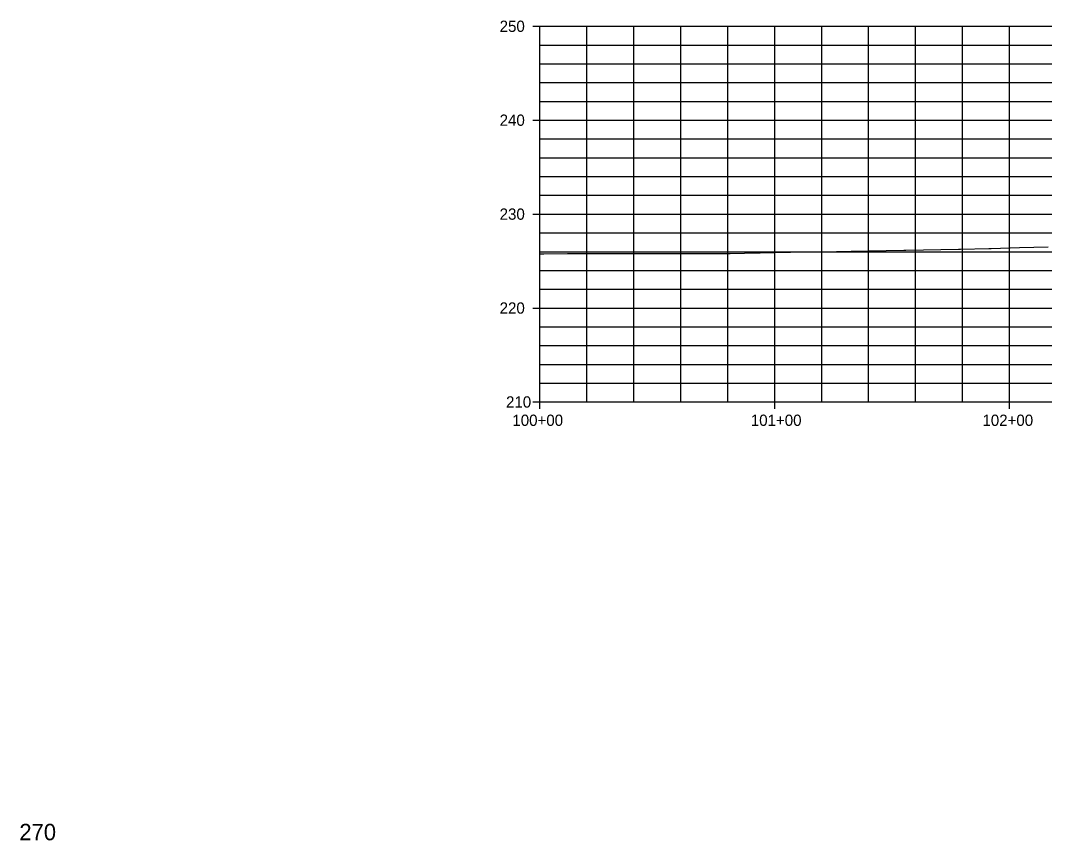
# Model space of a CAD drawing. Extents: x 1805251 to 1808760, y 516965 to 518393.
# Drawn here: x 1805251 to 1805687.1, y 518043.6 to 518392.9 of the extents above; entities that cross this region are included whole.
import ezdxf

# ---------------------------------------------------------------- set-up
doc = ezdxf.new("R2010")
doc.units = 0
for name, color, linetype in [('R_Axis', 7, 'Continuous'), ('R_Axis Annot', 7, 'Continuous'), ('R_Exist Surface', 7, 'Continuous'), ('R_Grid', 7, 'Continuous')]:
    doc.layers.add(name, color=color, linetype=linetype)

msp = doc.modelspace()

# ---------------------------------------------------------------- linework, layer by layer
at = {"layer": 'R_Axis'}
for q in [(1805472.2, 518390.42), (1806472.2, 518230.42)]:
    msp.add_line((1805472.2, 518230.42), q, dxfattribs=at)
at = {"layer": 'R_Exist Surface'}
msp.add_lwpolyline([(1805472.2, 518293.56), (1805473.66, 518293.55), (1805473.75, 518293.55), (1805473.84, 518293.55), (1805483.93, 518293.58), (1805493.56, 518293.59), (1805493.66, 518293.59), (1805513.21, 518293.6), (1805513.49, 518293.61), (1805513.76, 518293.61), (1805533.11, 518293.63), (1805533.57, 518293.64), (1805552.54, 518293.66), (1805553.18, 518293.67), (1805565.47, 518293.9), (1805566.06, 518293.91), (1805578.4, 518294.15), (1805578.94, 518294.16), (1805591.32, 518294.39), (1805591.82, 518294.4), (1805592.32, 518294.41), (1805604.7, 518294.65), (1805627.18, 518295.06), (1805628, 518295.07), (1805650.5, 518295.48), (1805651.29, 518295.5), (1805663.45, 518295.82), (1805664.33, 518295.84), (1805676.49, 518296.16), (1805688.59, 518296.47)], dxfattribs=at)
at = {"layer": 'R_Grid'}
for p, q in [((1805469.2, 518390.42), (1805472.2, 518390.42)), ((1805469.2, 518390.42), (1805472.2, 518390.42)), ((1805472.2, 518390.42), (1806472.2, 518390.42)), ((1805472.2, 518390.42), (1806472.2, 518390.42)), ((1805492.2, 518230.42), (1805492.2, 518390.42)), ((1805512.2, 518230.42), (1805512.2, 518390.42)), ((1805532.2, 518230.42), (1805532.2, 518390.42)), ((1805552.2, 518230.42), (1805552.2, 518390.42)), ((1805572.2, 518230.42), (1805572.2, 518390.42)), ((1805592.2, 518230.42), (1805592.2, 518390.42)), ((1805612.2, 518230.42), (1805612.2, 518390.42)), ((1805632.2, 518230.42), (1805632.2, 518390.42)), ((1805652.2, 518230.42), (1805652.2, 518390.42)), ((1805672.2, 518230.42), (1805672.2, 518390.42)), ((1805472.2, 518382.42), (1805473.7, 518382.42)), ((1805472.2, 518382.42), (1806472.2, 518382.42)), ((1805472.2, 518374.42), (1805473.7, 518374.42)), ((1805472.2, 518374.42), (1806472.2, 518374.42)), ((1805472.2, 518366.42), (1805473.7, 518366.42)), ((1805472.2, 518366.42), (1806472.2, 518366.42)), ((1805472.2, 518358.42), (1805473.7, 518358.42)), ((1805472.2, 518358.42), (1806472.2, 518358.42)), ((1805469.2, 518350.42), (1805472.2, 518350.42)), ((1805472.2, 518350.42), (1806472.2, 518350.42)), ((1805472.2, 518342.42), (1805473.7, 518342.42)), ((1805472.2, 518342.42), (1806472.2, 518342.42)), ((1805472.2, 518334.42), (1805473.7, 518334.42)), ((1805472.2, 518334.42), (1806472.2, 518334.42)), ((1805472.2, 518326.42), (1805473.7, 518326.42)), ((1805472.2, 518326.42), (1806472.2, 518326.42)), ((1805472.2, 518318.42), (1805473.7, 518318.42)), ((1805472.2, 518318.42), (1806472.2, 518318.42)), ((1805469.2, 518310.42), (1805472.2, 518310.42)), ((1805472.2, 518310.42), (1806472.2, 518310.42)), ((1805472.2, 518302.42), (1805473.7, 518302.42)), ((1805472.2, 518302.42), (1806472.2, 518302.42)), ((1805472.2, 518294.42), (1805473.7, 518294.42)), ((1805472.2, 518294.42), (1806472.2, 518294.42)), ((1805472.2, 518286.42), (1805473.7, 518286.42)), ((1805472.2, 518286.42), (1806472.2, 518286.42)), ((1805472.2, 518278.42), (1805473.7, 518278.42)), ((1805472.2, 518278.42), (1806472.2, 518278.42)), ((1805469.2, 518270.42), (1805472.2, 518270.42)), ((1805472.2, 518270.42), (1806472.2, 518270.42)), ((1805472.2, 518262.42), (1805473.7, 518262.42)), ((1805472.2, 518262.42), (1806472.2, 518262.42)), ((1805472.2, 518254.42), (1805473.7, 518254.42)), ((1805472.2, 518254.42), (1806472.2, 518254.42)), ((1805472.2, 518246.42), (1805473.7, 518246.42)), ((1805472.2, 518246.42), (1806472.2, 518246.42)), ((1805472.2, 518238.42), (1805473.7, 518238.42)), ((1805472.2, 518238.42), (1806472.2, 518238.42)), ((1805469.2, 518230.42), (1805472.2, 518230.42)), ((1805472.2, 518227.42), (1805472.2, 518230.42)), ((1805572.2, 518227.42), (1805572.2, 518230.42)), ((1805672.2, 518227.42), (1805672.2, 518230.42))]:
    msp.add_line(p, q, dxfattribs=at)

# ---------------------------------------------------------------- texts
at = {"layer": 'R_Axis Annot'}
for s, height, p in [('250', 4.8, (1805455.05, 518388.02)), ('240', 4.8, (1805455.05, 518348.02)), ('230', 4.8, (1805455.05, 518308.02)), ('220', 4.8, (1805455.05, 518268.02)), ('210', 4.8, (1805457.77, 518228.02)), ('-', 0.0001, (1805472.2, 518230.42)), ('100+00', 4.8, (1805460.47, 518220.22)), ('101+00', 4.8, (1805562.02, 518220.22)), ('102+00', 4.8, (1805660.66, 518220.22)), ('270', 7, (1805250.51, 518043.74)), ('270', 7, (1805250.51, 518043.74))]:
    msp.add_text(s, height=height, dxfattribs=at).set_placement(p)

doc.saveas('drawing.dxf')
